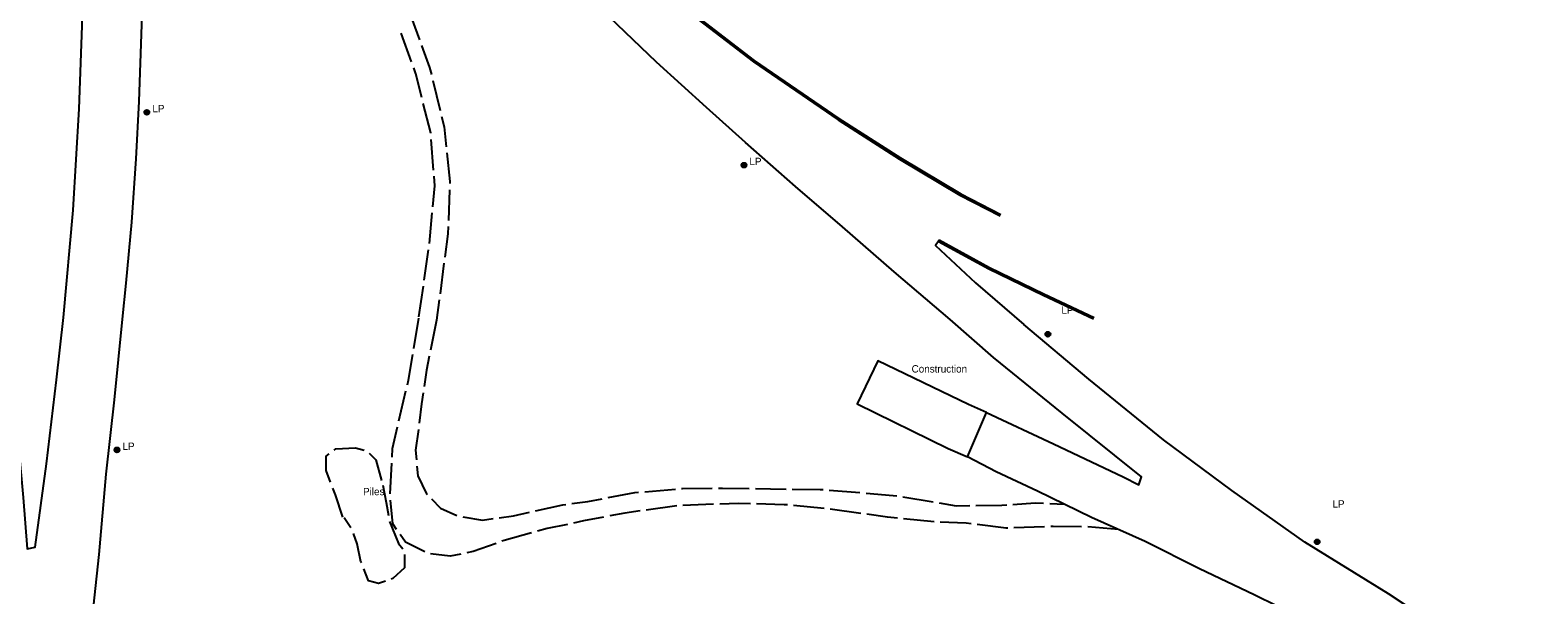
# Model space of a CAD drawing. Extents: x 2402803 to 2427059, y 6985292 to 6997652.
# Drawn here: x 2410720 to 2411699, y 6992646 to 6993013 of the extents above; entities that cross this region are included whole.
import ezdxf

# ---------------------------------------------------------------- set-up
doc = ezdxf.new("R2010")
doc.units = 0
for name, color, linetype in [('p_dtm stock pile', 7, 'Continuous'), ('p_road - paved curb', 7, 'Continuous'), ('p_road dirt road', 7, 'Continuous'), ('p_structure ruins', 7, 'Continuous'), ('p_utility manhole', 7, 'Continuous')]:
    doc.layers.add(name, color=color, linetype=linetype)

msp = doc.modelspace()

# ---------------------------------------------------------------- linework, layer by layer
at = {"layer": 'p_dtm stock pile'}
msp.add_line((2410928.2, 6992689.25), (2410923.87, 6992695.63), dxfattribs=at)
for points in [[(2410917.31, 6992739.77), (2410918.38, 6992740.59), (2410931.19, 6992741.29), (2410936.8, 6992739.74)], [(2410915.05, 6992718.84), (2410912.15, 6992726.44), (2410912.17, 6992735.81), (2410914.14, 6992737.33)], [(2410940.15, 6992737.83), (2410944.38, 6992733.38), (2410948.05, 6992720.04)], [(2410923.04, 6992696.21), (2410918.17, 6992710.64), (2410916.47, 6992715.1)], [(2410948.9, 6992716.97), (2410951.18, 6992705.78), (2410952.54, 6992697.31)], [(2410953.28, 6992693.39), (2410959.14, 6992679.02), (2410961.89, 6992675.49)], [(2410935.05, 6992666.38), (2410934.71, 6992667.24), (2410932.31, 6992678.84), (2410929.86, 6992685.64)], [(2410963.03, 6992671.89), (2410962.97, 6992663.21), (2410955.49, 6992656.34), (2410954.41, 6992655.95)], [(2410950.64, 6992654.6), (2410946.12, 6992652.98), (2410939.66, 6992654.77), (2410936.53, 6992662.66)]]:
    msp.add_lwpolyline(points, dxfattribs=at)
at = {"layer": 'p_road - paved curb'}
for points in [[(2410741.61, 6992826.02), (2410747.83, 6992895.57), (2410751.8, 6992961.6), (2410753.85, 6993021.62), (2410753.73, 6993087.24), (2410751.62, 6993154), (2410748.47, 6993225.36), (2410744.95, 6993277.46), (2410739.67, 6993333.06), (2410739.78, 6993333.65), (2410732.25, 6993404.63), (2410725.5, 6993459.29), (2410718.97, 6993509.93), (2410712.31, 6993558.83), (2410703.69, 6993610.23), (2410694.62, 6993664.96), (2410685.34, 6993713.02), (2410674.64, 6993766.89), (2410663.97, 6993813.71), (2410654.74, 6993854.5), (2410643.68, 6993898.31), (2410630.27, 6993950.34), (2410611.59, 6994020.31)], [(2410817.36, 6993378.43), (2410812.85, 6993377.9), (2410795.95, 6993419.89), (2410780.43, 6993461.86), (2410774.5, 6993484), (2410761.64, 6993481.57), (2410767.66, 6993436.99), (2410772.02, 6993397.98), (2410776.55, 6993346.19), (2410782.25, 6993289.92), (2410785.37, 6993243.96), (2410788.68, 6993191.83), (2410790.11, 6993157.32), (2410792.36, 6993112.02), (2410792.46, 6993059.64), (2410792.31, 6993016.31), (2410790.42, 6992966.33), (2410788.49, 6992929.02), (2410785.78, 6992887.8), (2410782.14, 6992848.18), (2410779.61, 6992824.88)], [(2410816.97, 6993478.96), (2410822.01, 6993462.2), (2410826.45, 6993448.51), (2410837.58, 6993418.34), (2410853.97, 6993380.33), (2410869.14, 6993349.32), (2410882.16, 6993324.41), (2410901.07, 6993291.82), (2410923.62, 6993257.33), (2410947.55, 6993224.98), (2410972.08, 6993194.42), (2411003.14, 6993158.37), (2411032.04, 6993128.81), (2411065.12, 6993096.23), (2411112.3, 6993054.23), (2411144.26, 6993028.2), (2411190.25, 6992992.96), (2411245.2, 6992955.15), (2411285.15, 6992929.75), (2411324.33, 6992906.35), (2411350.4, 6992892.78)], [(2411317.49, 6992824.55), (2411281.06, 6992855.57), (2411247.54, 6992884.91), (2411216.91, 6992910.99), (2411184.48, 6992939.55), (2411159.27, 6992962.45), (2411126.67, 6992991.89), (2411096.26, 6993021.03), (2411062.76, 6993053.04)], [(2411143.64, 6993027.42), (2411189.66, 6992992.15), (2411244.65, 6992954.32), (2411284.63, 6992928.9), (2411323.84, 6992905.48), (2411349.94, 6992891.89)], [(2411310.34, 6992876.07), (2411307.98, 6992872.77), (2411333.88, 6992848.53), (2411365.35, 6992821.37)], [(2411410.52, 6992824.86), (2411377.94, 6992840.17), (2411342.57, 6992857.3), (2411309.86, 6992875.19)], [(2411410.95, 6992825.77), (2411378.37, 6992841.07), (2411343.03, 6992858.19), (2411310.34, 6992876.07)], [(2410704.55, 6992829.57), (2410707.71, 6992797.62), (2410710.91, 6992759.1), (2410715.26, 6992708.91), (2410717.9, 6992675.6), (2410723.18, 6992676.67), (2410730.51, 6992730.81), (2410736.98, 6992785.35), (2410741.61, 6992826.02)], [(2410779.61, 6992824.88), (2410774.41, 6992772.43), (2410769.03, 6992724.05), (2410764.48, 6992671.9), (2410759.33, 6992623.63), (2410757.88, 6992589.4), (2410753.33, 6992537.66), (2410749.77, 6992498.36), (2410748.18, 6992475.31)], [(2411635.72, 6992587.79), (2411602.77, 6992601.84), (2411559.78, 6992623.54), (2411514.84, 6992645.6), (2411479.45, 6992662.62), (2411444.18, 6992680.31), (2411409.24, 6992695.94), (2411374.18, 6992713.14), (2411347.25, 6992725.6), (2411328.66, 6992735.32), (2411341.16, 6992764.27), (2411384.51, 6992743.84), (2411429.79, 6992722.39), (2411440.1, 6992717.25), (2411441.77, 6992722.36), (2411390.3, 6992763.82), (2411345.68, 6992799.84), (2411317.49, 6992824.55)], [(2411699.17, 6992591.05), (2411644.58, 6992618.08), (2411602.24, 6992646.24), (2411547.72, 6992680.02), (2411500.32, 6992713.51), (2411456.06, 6992746.48), (2411407.42, 6992785.87), (2411365.35, 6992821.37)]]:
    msp.add_lwpolyline(points, dxfattribs=at)
at = {"layer": 'p_road dirt road'}
for p, q in [((2410965.79, 6993025.2), (2410972.7, 6993006.44)), ((2410967.67, 6992991.97), (2410960.89, 6993010.78)), ((2410981.44, 6992979.88), (2410986.22, 6992960.46)), ((2410981.94, 6992921.72), (2410980.39, 6992941.66)), ((2410992.3, 6992908.98), (2410991.51, 6992889)), ((2410979.2, 6992873.93), (2410981.07, 6992893.83)), ((2410975.86, 6992850.16), (2410978.72, 6992869.96)), ((2410988.69, 6992861.17), (2410986.12, 6992841.33)), ((2410972.44, 6992826.41), (2410975.29, 6992846.21)), ((2410985.61, 6992837.37), (2410983.91, 6992824.2)), ((2410969.01, 6992805.77), (2410972.29, 6992825.5)), ((2410983.91, 6992824.2), (2410979.89, 6992804.61)), ((2410959.44, 6992758.76), (2410963.97, 6992778.24)), ((2410953.75, 6992711.28), (2410954.77, 6992731.25)), ((2411119.04, 6992712.65), (2411138.96, 6992714.39)), ((2411238.89, 6992713.74), (2411258.82, 6992712.09)), ((2411139.82, 6992703.43), (2411120.01, 6992700.73)), ((2411163.78, 6992704.55), (2411143.8, 6992703.82)), ((2411235.63, 6992701.78), (2411215.72, 6992703.69)), ((2411259.41, 6992698.61), (2411239.6, 6992701.35)), ((2411286.66, 6992709.28), (2411306.4, 6992706.04)), ((2411382.09, 6992705.03), (2411391.75, 6992704.57)), ((2411307.08, 6992693.06), (2411287.19, 6992695.13)), ((2411378.83, 6992689.87), (2411358.85, 6992689.23))]:
    msp.add_line(p, q, dxfattribs=at)
for points in [[(2410974.08, 6993002.68), (2410979.36, 6992988.36), (2410980.49, 6992983.76)], [(2410974.29, 6992968.93), (2410970.41, 6992984.36), (2410969.02, 6992988.21)], [(2410980.09, 6992945.65), (2410980.06, 6992945.98), (2410975.26, 6992965.05)], [(2410987.17, 6992956.58), (2410988.82, 6992949.88), (2410990.18, 6992936.85)], [(2410990.59, 6992932.87), (2410992.52, 6992914.4), (2410992.46, 6992912.97)], [(2410981.45, 6992897.81), (2410982.73, 6992911.47), (2410982.25, 6992917.73)], [(2410991.35, 6992885), (2410991.17, 6992880.37), (2410989.2, 6992865.13)], [(2410964.88, 6992782.13), (2410965.57, 6992785.11), (2410968.35, 6992801.82)], [(2410979.08, 6992800.69), (2410977.25, 6992791.77), (2410975.72, 6992780.99)], [(2410975.16, 6992777.03), (2410974.13, 6992769.75), (2410972.53, 6992757.2)], [(2410954.97, 6992735.25), (2410955.25, 6992740.75), (2410958.53, 6992754.86)], [(2410972.03, 6992753.23), (2410970.29, 6992739.6), (2410970.81, 6992733.37)], [(2410971.14, 6992729.38), (2410971.67, 6992723.02), (2410977.42, 6992711.34), (2410977.83, 6992710.91)], [(2411095.37, 6992708.87), (2411112.65, 6992712.09), (2411115.06, 6992712.3)], [(2411142.95, 6992714.74), (2411143.57, 6992714.79), (2411162.94, 6992715.03)], [(2411166.94, 6992715.08), (2411169.6, 6992715.11), (2411186.94, 6992714.81)], [(2411190.93, 6992714.74), (2411200.83, 6992714.57), (2411210.93, 6992714.46)], [(2411214.93, 6992714.42), (2411232.99, 6992714.23), (2411232.99, 6992714.23), (2411234.9, 6992714.07)], [(2411262.81, 6992711.76), (2411280.4, 6992710.31), (2411282.72, 6992709.93)], [(2410957.9, 6992688.16), (2410955.36, 6992691.79), (2410953.97, 6992707.29)], [(2410980.61, 6992708.03), (2410986.44, 6992701.97), (2410997.05, 6992697.35)], [(2411048.18, 6992700.23), (2411065.98, 6992704.15), (2411067.74, 6992704.39)], [(2411071.7, 6992704.95), (2411082.2, 6992706.41), (2411091.43, 6992708.13)], [(2411116.04, 6992700.19), (2411106.14, 6992698.84), (2411096.31, 6992696.96)], [(2411187.76, 6992704.9), (2411179.94, 6992705.13), (2411167.78, 6992704.69)], [(2411211.74, 6992704.07), (2411209.68, 6992704.27), (2411191.76, 6992704.79)], [(2411310.35, 6992705.39), (2411321.25, 6992703.6), (2411330.2, 6992703.7)], [(2411334.2, 6992703.75), (2411351.05, 6992703.94), (2411354.18, 6992704.17)], [(2411358.17, 6992704.45), (2411372.6, 6992705.49), (2411378.11, 6992705.23)], [(2411000.91, 6992696.4), (2411013.71, 6992694.23), (2411020.66, 6992695.21)], [(2411024.62, 6992695.76), (2411033.77, 6992697.05), (2411044.28, 6992699.37)], [(2411068.85, 6992691.5), (2411055.6, 6992688.7), (2411049.38, 6992686.98)], [(2411092.39, 6992696.21), (2411079.32, 6992693.71), (2411072.77, 6992692.33)], [(2411283.21, 6992695.54), (2411276.73, 6992696.21), (2411263.37, 6992698.06)], [(2411331.03, 6992691.93), (2411327.83, 6992692.33), (2411311.07, 6992692.85)], [(2411354.85, 6992689.1), (2411353.8, 6992689.07), (2411335, 6992691.43)], [(2410976.17, 6992673.73), (2410963.61, 6992679.98), (2410960.19, 6992684.88)], [(2411045.53, 6992685.91), (2411027.79, 6992680.99), (2411026.29, 6992680.46)], [(2411402.81, 6992689.94), (2411384.34, 6992690.04), (2411382.83, 6992689.99)], [(2411426.71, 6992688.12), (2411406.93, 6992689.92), (2411406.81, 6992689.92)], [(2410999.6, 6992672.17), (2410992.8, 6992670.73), (2410979.85, 6992672.28)], [(2411022.52, 6992679.13), (2411007.56, 6992673.86), (2411003.51, 6992673)]]:
    msp.add_lwpolyline(points, dxfattribs=at)
at = {"layer": 'p_structure ruins'}
msp.add_lwpolyline([(2411341.16, 6992764.27), (2411329.39, 6992769.38), (2411270.42, 6992797.69), (2411257.07, 6992769.79), (2411316.18, 6992740.84), (2411328.66, 6992735.32)], dxfattribs=at)
at = {"layer": 'p_utility manhole'}
for centre, radius in [((2410795.7, 6992959.29), 1.6), ((2410795.7, 6992959.29), 1.3), ((2410795.7, 6992959.29), 1), ((2410795.7, 6992959.29), 0.539), ((2410795.7, 6992959.29), 0.192), ((2411183.51, 6992924.93), 1.6), ((2411183.51, 6992924.93), 1.3), ((2411183.51, 6992924.93), 1), ((2411183.51, 6992924.93), 0.539), ((2411183.51, 6992924.93), 0.192), ((2411380.94, 6992815.06), 1.6), ((2411380.94, 6992815.06), 1.3), ((2411380.94, 6992815.06), 1), ((2411380.94, 6992815.06), 0.539), ((2411380.94, 6992815.06), 0.192), ((2410776.28, 6992739.86), 1.6), ((2410776.28, 6992739.86), 1.3), ((2410776.28, 6992739.86), 1), ((2410776.28, 6992739.86), 0.539), ((2410776.28, 6992739.86), 0.192), ((2411555.84, 6992680.15), 1.6), ((2411555.84, 6992680.15), 1.3), ((2411555.84, 6992680.15), 1), ((2411555.84, 6992680.15), 0.539), ((2411555.84, 6992680.15), 0.192)]:
    msp.add_circle(centre, radius, dxfattribs=at)

# ---------------------------------------------------------------- texts
at = {"layer": 'p_dtm stock pile'}
msp.add_text('Piles', height=4.8, dxfattribs=at).set_placement((2410936.11, 6992710.41))
at = {"layer": 'p_structure ruins'}
msp.add_text('Construction', height=4.8, dxfattribs=at).set_placement((2411292.41, 6992790.15))
at = {"layer": 'p_utility manhole'}
for p in [(2410795.7, 6992959.29), (2411183.51, 6992924.93), (2411386.16, 6992828.34), (2410776.28, 6992739.86), (2411562.21, 6992702.36)]:
    msp.add_text('  LP', height=4.8, dxfattribs=at).set_placement(p)

doc.saveas('drawing.dxf')
